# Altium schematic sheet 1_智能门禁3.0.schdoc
size 309 x 223 mm; Symbol: Sheet-Symbol_A4; Device: Sheet-Symbol_A4; Company: 嘉立创EDA; Version: V1.0; Page Size: A4; @Project Name: 智能门禁3.0; @Page Count: 1; @Update Date: 2024-07-30; @Create Date: 2023-10-07; @Schematic Name: 智能门禁3.0; @Page No: 1; @Page Name: 智能门禁3.0
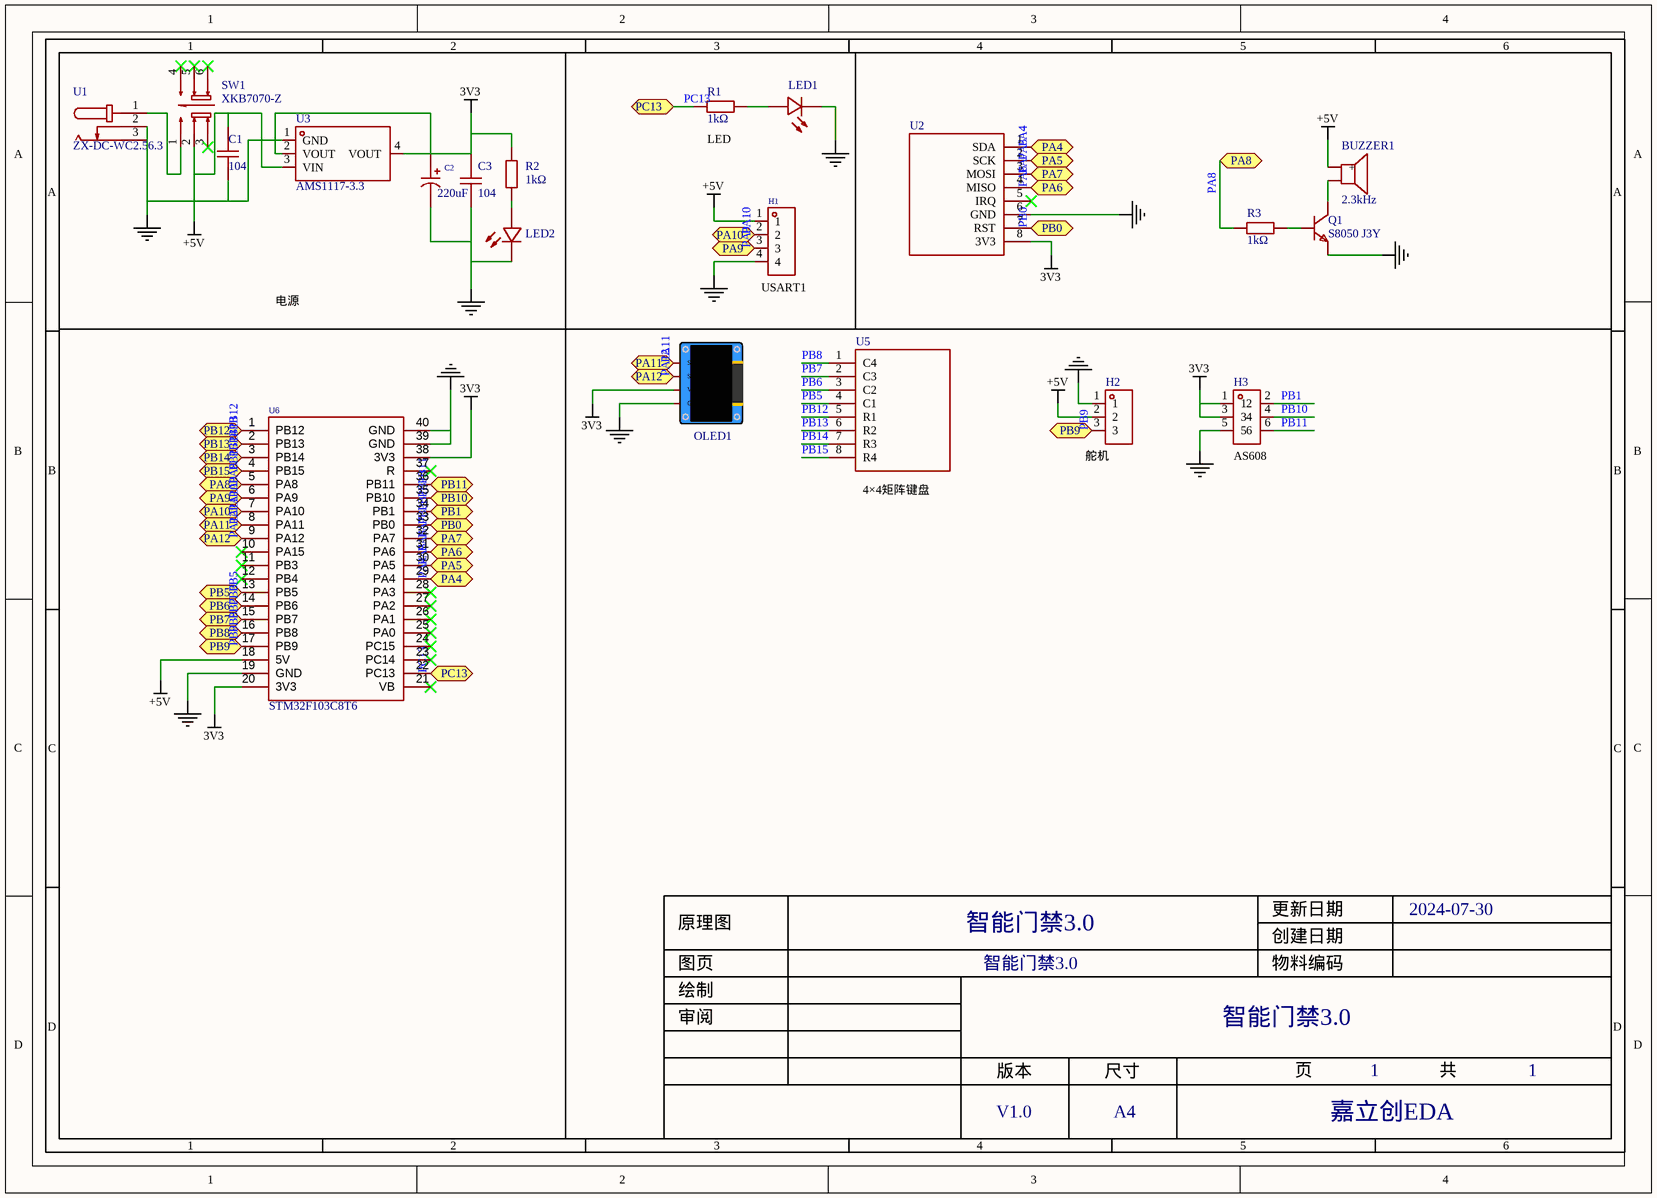
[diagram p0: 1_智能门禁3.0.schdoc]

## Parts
BUZZER1  2.3kHz  [BUZ-TH_BD12.0-P7.60-D0.6-FD]  (value not drawn)
C1  104  [C0805]  (value not drawn)
C2  220uF  [CAP-SMD_BD6.3-L6.6-W6.6-FD]  (value not drawn)
C3  104  [C0805]  (value not drawn)
H1  PZ254V-11-04P  [HDR-TH_4P-P2.54-V-M]  (value not drawn)
H2  红外对管  [HDR-TH_3P-P2.54-V-F]  (value not drawn)
H3  PZ254V-12-6P  [HDR-TH_6P-P2.54-V-M-R2-C3-S2.54]  (value not drawn)
LED1  204-10SUGD/S400-A4-L  [LED-TH_BD3.9-P2.54-RD]  (value not drawn)
LED2  204-10SUGD/S400-A4-L  [LED-TH_BD3.9-P2.54-RD]  (value not drawn)
OLED1  0.96OLED模块_4P  [0.96OLED_4P]  (value not drawn)
Q1  S8050 J3Y  [SOT-23-3_L3.0-W1.7-P0.95-LS2.9-BR]  (value not drawn)
R1  1kΩ  [R0805]  (value not drawn)
R2  1kΩ  [R0805]  (value not drawn)
R3  1kΩ  [R0805]  (value not drawn)
SW1  XKB7070-Z  [SW-TH_6P-L7.0-W7.0-P2.00]  (value not drawn)
U1  ZX-DC-WC2.56.3  [DC-TH_ZX-DC-WC2.56.3]  (value not drawn)
U2  RC522  [RC522]  (value not drawn)
U3  AMS1117-3.3  [SOT-223-3_L6.5-W3.4-P2.30-LS7.0-BR]  (value not drawn)
U5  矩阵键盘  [矩阵键盘]  (value not drawn)
U6  STM32F103C8T6  [STM32F103C8T6]  (value not drawn)

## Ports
PA4 (bidir), PA5 (bidir), PA6 (bidir), PA7 (bidir), PA8 (bidir), PA9 (bidir), PA10 (bidir), PA11 (bidir), PA12 (bidir), PB0 (bidir), PB1 (bidir), PB5 (bidir), PB6 (bidir), PB7 (bidir), PB8 (bidir), PB9 (bidir), PB10 (bidir), PB11 (bidir), PB12 (bidir), PB13 (bidir), PB14 (bidir), PB15 (bidir), PC13 (bidir)

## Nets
3V3: C2.1 C3.1 H3.1 H3.3 OLED1.2(VCC) R2.2 U2.8(3V3) U3.2(VOUT) U3.4(VOUT) U6.20(3V3) U6.38(3V3)
+5V: BUZZER1.1(+) C1.1 H1.1 H2.2 SW1.2 U3.3(VIN) U6.18(5V)
GND: C1.2 C2.2 C3.2 H1.4 H2.1 H3.5 LED1.1(-) LED2.1(-) OLED1.1(GND) Q1.2(E) U1.2 U1.3 U2.6(GND) U3.1(GND) U6.19(GND) U6.39(GND) U6.40(GND)
PA4: U2.1(SDA) U6.29(PA4) ; port PA4
PA5: U2.2(SCK) U6.30(PA5) ; port PA5
PA6: U2.4(MISO) U6.31(PA6) ; port PA6
PA7: U2.3(MOSI) U6.32(PA7) ; port PA7
PA8: R3.2 U6.5(PA8) ; port PA8
PA9: H1.3 U6.6(PA9) ; port PA9
PA10: H1.2 U6.7(PA10) ; port PA10
PA11: OLED1.4(SDA) U6.8(PA11) ; port PA11
PA12: OLED1.3(SCL) U6.9(PA12) ; port PA12
PB0: U2.7(RST) U6.33(PB0) ; port PB0
PB1: H3.2 U6.34(PB1) ; port PB1
PB5: U5.4(C1) U6.13(PB5) ; port PB5
PB6: U5.3(C2) U6.14(PB6) ; port PB6
PB7: U5.2(C3) U6.15(PB7) ; port PB7
PB8: U5.1(C4) U6.16(PB8) ; port PB8
PB9: H2.3 U6.17(PB9) ; port PB9
PB10: H3.4 U6.35(PB10) ; port PB10
PB11: H3.6 U6.36(PB11) ; port PB11
PB12: U5.5(R1) U6.1(PB12) ; port PB12
PB13: U5.6(R2) U6.2(PB13) ; port PB13
PB14: U5.7(R3) U6.3(PB14) ; port PB14
PB15: U5.8(R4) U6.4(PB15) ; port PB15
PC13: R1.2 U6.22(PC13) ; port PC13
NetBUZZER1_2: BUZZER1.2 Q1.3(C)
NetLED1_2: LED1.2(+) R1.1
NetLED2_2: LED2.2(+) R2.1
NetQ1_1: Q1.1(B) R3.1
NetSW1_1: SW1.1 U1.1

Not connected (* = marked no-connect by the designer): SW1 3* 4* 5* 6*; U2 5(IRQ)*; U6 10(PA15)* 11(PB3)* 12(PB4)* 21(VB)* 23(PC14)* 24(PC15)* 25(PA0)* 26(PA1)* 27(PA2)* 28(PA3)* 37(R)*

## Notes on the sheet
- (near R1) LED
- 电源
- (near H1) USART1
- (near H2) 舵机
- (near H3) AS608
- (near U5) 4×4矩阵键盘

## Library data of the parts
BUZZER1 = TMB12A03: 驱动方式:有源(内含驱动线路);构造类型:电磁式;频率:2.3kHz;声压(SPL):85dB;; Manufacturer: 华能; Symbol: TMB12A05; Add into BOM: yes; Technology Type: 电磁式; Operating Voltage: 1.5V~4V; Sound Pressure Level (SPL): 85dB; Rated Voltage: 5V
C1 C3 = CC0805JRX7R7BB104: 容值:100nF;精度:±5%;额定电压:16V;材质(温度系数):X7R;; Manufacturer: YAGEO(国巨); Add into BOM: yes; Tolerance: ±5%; Voltage Rated: 16V; Temperature Coefficient: X7R
C2 = RVT220UF16V67RV0015: 容值:220uF;精度:±20%;额定电压:16V;纹波电流:110mA@120Hz;等效串联电阻:-;; Manufacturer: KNSCHA(科尼盛); Add into BOM: yes; Tolerance: ±20%; Rated Voltage: 16V; φD: 6.3mm; L: 7.7mm; Lifetime @ Temp: 2000hrs@105℃
H1 = PZ254V-11-04P: 排数:单排;总PIN位数:4P;间距:2.54mm;插针结构:1x4P;行距:-;安装类型:直插;圆针/方针:方针;额定电流:3A;额定电压:250V;配合针长度:6mm;塑高:2.5mm;端接针长度:3mm;触头材质:-;工作温度范围:-40℃~+105℃;颜色:黑色;; Manufacturer: XFCN(兴飞); Symbol: PZ254V-11-04P_C2691448; Add into BOM: yes; Pitch: 2.54mm; Pin Structure: 1x4P; Circluar Pins/Square Pins: 方针; Current Rating (Max): 3A; Voltage Rating (Max): 250V
H2 = PM254V-11-03-H85: 排数:单排;总孔位数:3P;间距:2.54mm;插孔结构:1x3P;行距:-;安装类型:直插;塑高:-;触头材质:黄铜;触头镀层:-;; Manufacturer: XFCN(兴飞); Add into BOM: yes; Number of Holes: 3P; Pitch: 2.54mm; Holes Structure: 1x3P
H3 = PZ254V-12-6P: 插针结构:2x3P;间距:2.54mm;行距:2.54mm;圆针/方针:方针;安装类型:直插;排数:双排;总PIN位数:6P;额定电流:-;额定电压:-;配合针长度:6mm;塑高:2.5mm;端接针长度:3mm;触头材质:黄铜;触头镀层:-;工作温度范围:-40℃~+105℃;颜色:黑色;; Manufacturer: XFCN(兴飞); Add into BOM: yes; Pin Structure: 2x3P; Pitch: 2.54mm; Circluar Pins/Square Pins: 方针
LED1 LED2 = 204-10SUGD/S400-A4-L: Manufacturer: EVERLIGHT(亿光); Add into BOM: yes
OLED1 = 0.96OLED模块_4P: Convert to PCB: yes
Q1 = S8050 J3Y_C2146: 晶体管类型:NPN;集电极电流(Ic):500mA;集射极击穿电压(Vceo):25V;功率(Pd):300mW;直流电流增益(hFE@Ic,Vce):200@50mA,1V;; Manufacturer: CJ(江苏长电/长晶); Symbol: S8050_C2146; Add into BOM: yes; Transistor Type: NPN; Collector Current (Ic): 500mA; Collector-Emitter Breakdown Voltage (Vceo): 25V; Power Dissipation (Pd): 300mW; Transition Frequency (fT): 150MHz; Collector Cut-Off Current (Icbo): 100nA; Collector-Emitter Saturation Voltage (VCE(sat)@Ic,Ib): 600mV@500mA,50mA
R1-R3 = 0805W8F1001T5E: 阻值:1kΩ;精度:±1%;功率:125mW;温度系数:±100ppm/℃;电阻类型:厚膜电阻;; Manufacturer: UNI-ROYAL(厚声); Add into BOM: yes; Tolerance: ±1%; Power(Watts): 125mW; Overload Voltage (Max): 150V
SW1 = XKB7070-Z: 触点电流:100mA;额定电压 (AC):250V;额定电压 (DC):30V;绝缘电阻:100MΩ;安装方式:直插;自锁/无锁:自锁;按键形状:矩形按钮;按键/盖帽颜色:蓝色;带灯:无;引脚样式:PC引脚;作用力:160gf@±80gf;防护等级:-;工作温度:-15℃~+55℃;机械寿命:100000;; Manufacturer: XKB Connectivity(中国星坤); Add into BOM: yes; Contact Current: 100mA; Voltage Rating (AC): 250V; Voltage Rating (DC): 30V; Insulation Resistance: 100MΩ; Self Lock / No Lock: 自锁; Actuator Style: 矩形按钮; Actuator/Cap Color: 蓝色; With Lamp: 无; Pin Style: PC引脚; Mechanical Life: 100000
U1 = ZX-DC-WC2.56.3: AC/DC电源连接器  DC电源插座 内径:2.5mm 外径:6.3mmDC-005 外径6.3 内芯2.5 5A电流 DC电源插座; Manufacturer: Megastar(兆星); Add into BOM: yes
U2 = RC522: Add into BOM: yes
U3 = AMS1117-3.3_C6186: 输出类型:固定;输出极性:正;最大输入电压:-;输出电压:3.3V;输出电流:1A;电源纹波抑制比(PSRR):72dB@(120Hz);; Manufacturer: AMS; Add into BOM: yes; Output Type: 固定; Output Polarity: 正; Number of Outputs: 1; Output Voltage: 3.3V; Dropout Voltage: 1.3V@(800mA); Output Current: 1A
U5 = 矩阵键盘: Add into BOM: yes
U6 = STM32F103C8T6: Convert to PCB: yes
